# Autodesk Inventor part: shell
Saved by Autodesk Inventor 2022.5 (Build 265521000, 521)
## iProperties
Created: 2024-12
Part Number: shell
Material: Generic
Document SubType Name: Modeling
Designer: AdminForWorker
Density: 1 g/cm^3
Appearance: Default
Title: shell
Author: AdminForWorker
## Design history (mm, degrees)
feature "Body1"
body "Solid1"
